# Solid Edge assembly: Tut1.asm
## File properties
Author: CADCIM
Template: ansi assembly.asm
Last saved by: TIET
Revision: 6
Application: Solid Edge
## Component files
support_roller_bracket.par
stock_support_roller.par
adjusting_nut_handle.par
adjusting_screw_guide.par
Stock_support_base.par
thrust_bearing.par
adjusting_screw_nut.par
support_adjusting_screw.par
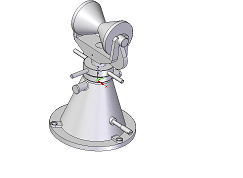
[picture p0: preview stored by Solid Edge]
